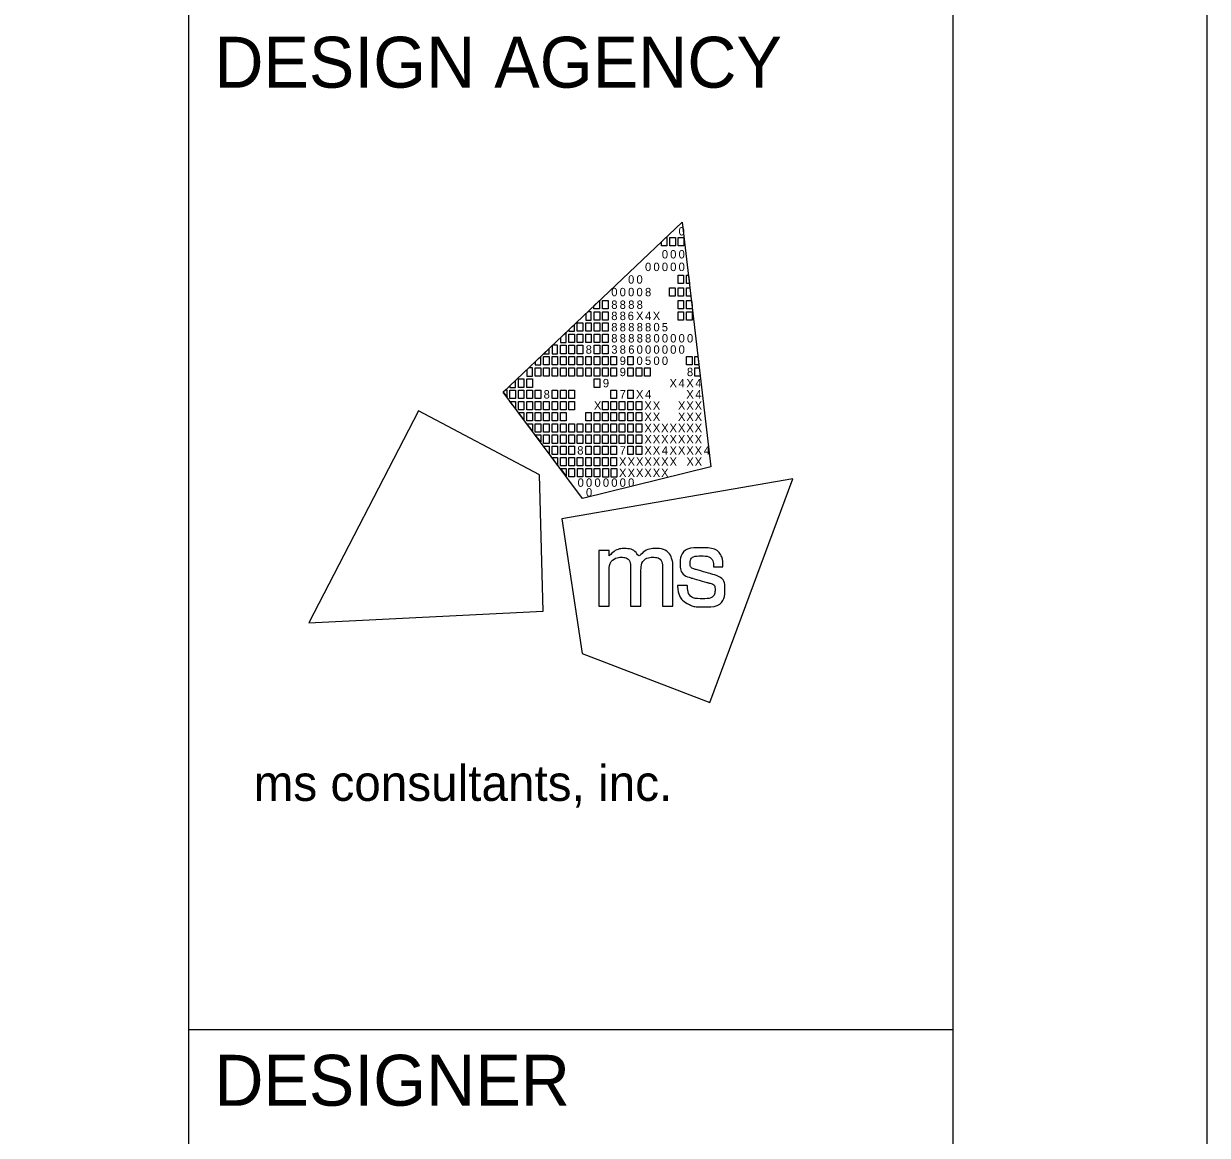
# Model space of a CAD drawing. Extents: x -3.2 to 34, y 0 to 22.
# Drawn here: x 31.676 to 34, y 2.292 to 4.476 of the extents above; entities that cross this region are included whole.
import ezdxf

# ---------------------------------------------------------------- set-up
doc = ezdxf.new("R2010")
doc.units = 0
for name, color, linetype in [('Default', 7, 'Continuous'), ('SH_Border', 7, 'Continuous'), ('SH_Cut_Line', 7, 'Continuous'), ('SH_Data', 7, 'Continuous')]:
    doc.layers.add(name, color=color, linetype=linetype)

msp = doc.modelspace()

# ---------------------------------------------------------------- linework, layer by layer
at = {"layer": 'Default'}
for p, q in [((32.6175, 3.7519), (32.9688, 4.0861)), ((32.9688, 4.0861), (32.9688, 4.0861)), ((32.9688, 4.0861), (33.0253, 3.6052)), ((32.773, 3.543), (32.6175, 3.7519)), ((33.0253, 3.6052), (32.773, 3.543))]:
    msp.add_line(p, q, dxfattribs=at)
for points in [[(32.9279, 4.0472), (32.9369, 4.0558), (32.9389, 4.0558), (32.9389, 4.0393), (32.9279, 4.0393)], [(32.9444, 4.0558), (32.9554, 4.0558), (32.9554, 4.0393), (32.9444, 4.0393)], [(32.9609, 4.0558), (32.9719, 4.0558), (32.9719, 4.0393), (32.9609, 4.0393)], [(32.9606, 3.9815), (32.9716, 3.9815), (32.9716, 3.965), (32.9606, 3.965)], [(32.9771, 3.9815), (32.9811, 3.9815), (32.983, 3.965), (32.9771, 3.965)], [(32.9441, 3.9567), (32.9551, 3.9567), (32.9551, 3.9402), (32.9441, 3.9402)], [(32.9606, 3.9567), (32.9716, 3.9567), (32.9716, 3.9402), (32.9606, 3.9402)], [(32.9771, 3.9567), (32.984, 3.9567), (32.9859, 3.9402), (32.9771, 3.9402)], [(32.7953, 3.9211), (32.8064, 3.9316), (32.8064, 3.9154), (32.7953, 3.9154)], [(32.8123, 3.9319), (32.8233, 3.9319), (32.8233, 3.9154), (32.8123, 3.9154)], [(32.9606, 3.9319), (32.9716, 3.9319), (32.9716, 3.9154), (32.9606, 3.9154)], [(32.9771, 3.9319), (32.9869, 3.9319), (32.9881, 3.9218), (32.9881, 3.9154), (32.9771, 3.9154)], [(32.7958, 3.9099), (32.8068, 3.9099), (32.8068, 3.8934), (32.7958, 3.8934)], [(32.8123, 3.9099), (32.8233, 3.9099), (32.8233, 3.8934), (32.8123, 3.8934)], [(32.9606, 3.9099), (32.9716, 3.9099), (32.9716, 3.8934), (32.9606, 3.8934)], [(32.9771, 3.9099), (32.9881, 3.9099), (32.9881, 3.8934), (32.9771, 3.8934)], [(32.7627, 3.8879), (32.7737, 3.8879), (32.7737, 3.8714), (32.7627, 3.8714)], [(32.7793, 3.8879), (32.7903, 3.8879), (32.7903, 3.8714), (32.7793, 3.8714)], [(32.7958, 3.8879), (32.8068, 3.8879), (32.8068, 3.8714), (32.7958, 3.8714)], [(32.8123, 3.8879), (32.8233, 3.8879), (32.8233, 3.8714), (32.8123, 3.8714)], [(32.7462, 3.8659), (32.7572, 3.8659), (32.7572, 3.8494), (32.7462, 3.8494)], [(32.7627, 3.8659), (32.7737, 3.8659), (32.7737, 3.8494), (32.7627, 3.8494)], [(32.7793, 3.8659), (32.7903, 3.8659), (32.7903, 3.8494), (32.7793, 3.8494)], [(32.7958, 3.8659), (32.8068, 3.8659), (32.8068, 3.8494), (32.7958, 3.8494)], [(32.8123, 3.8659), (32.8233, 3.8659), (32.8233, 3.8494), (32.8123, 3.8494)], [(32.7297, 3.8439), (32.7407, 3.8439), (32.7407, 3.8273), (32.7297, 3.8273)], [(32.7462, 3.8439), (32.7572, 3.8439), (32.7572, 3.8273), (32.7462, 3.8273)], [(32.7627, 3.8439), (32.7737, 3.8439), (32.7737, 3.8273), (32.7627, 3.8273)], [(32.7958, 3.8439), (32.8068, 3.8439), (32.8068, 3.8273), (32.7958, 3.8273)], [(32.8123, 3.8439), (32.8233, 3.8439), (32.8233, 3.8273), (32.8123, 3.8273)], [(32.6967, 3.8218), (32.7077, 3.8218), (32.7077, 3.8053), (32.6967, 3.8053)], [(32.7132, 3.8218), (32.7242, 3.8218), (32.7242, 3.8053), (32.7132, 3.8053)], [(32.7297, 3.8218), (32.7407, 3.8218), (32.7407, 3.8053), (32.7297, 3.8053)], [(32.7462, 3.8218), (32.7572, 3.8218), (32.7572, 3.8053), (32.7462, 3.8053)], [(32.7627, 3.8218), (32.7737, 3.8218), (32.7737, 3.8053), (32.7627, 3.8053)], [(32.7793, 3.8218), (32.7903, 3.8218), (32.7903, 3.8053), (32.7793, 3.8053)], [(32.7958, 3.8218), (32.8068, 3.8218), (32.8068, 3.8053), (32.7958, 3.8053)], [(32.8123, 3.8218), (32.8233, 3.8218), (32.8233, 3.8053), (32.8123, 3.8053)], [(32.8288, 3.8218), (32.8398, 3.8218), (32.8398, 3.8053), (32.8288, 3.8053)], [(32.8618, 3.8218), (32.8728, 3.8218), (32.8728, 3.8053), (32.8618, 3.8053)], [(32.9771, 3.8218), (32.9881, 3.8218), (32.9881, 3.8053), (32.9771, 3.8053)], [(32.9935, 3.8218), (32.9998, 3.8218), (33.0018, 3.8053), (32.9935, 3.8053)], [(32.6802, 3.7998), (32.6912, 3.7998), (32.6912, 3.7833), (32.6802, 3.7833)], [(32.6967, 3.7998), (32.7077, 3.7998), (32.7077, 3.7833), (32.6967, 3.7833)], [(32.7132, 3.7998), (32.7242, 3.7998), (32.7242, 3.7833), (32.7132, 3.7833)], [(32.7297, 3.7998), (32.7407, 3.7998), (32.7407, 3.7833), (32.7297, 3.7833)], [(32.7462, 3.7998), (32.7572, 3.7998), (32.7572, 3.7833), (32.7462, 3.7833)], [(32.7627, 3.7998), (32.7737, 3.7998), (32.7737, 3.7833), (32.7627, 3.7833)], [(32.7793, 3.7998), (32.7903, 3.7998), (32.7903, 3.7833), (32.7793, 3.7833)], [(32.7958, 3.7998), (32.8068, 3.7998), (32.8068, 3.7833), (32.7958, 3.7833)], [(32.8123, 3.7998), (32.8233, 3.7998), (32.8233, 3.7833), (32.8123, 3.7833)], [(32.8288, 3.7998), (32.8398, 3.7998), (32.8398, 3.7833), (32.8288, 3.7833)], [(32.8618, 3.7998), (32.8728, 3.7998), (32.8728, 3.7833), (32.8618, 3.7833)], [(32.8783, 3.7998), (32.8893, 3.7998), (32.8893, 3.7833), (32.8783, 3.7833)], [(32.8947, 3.7998), (32.9057, 3.7998), (32.9057, 3.7833), (32.8947, 3.7833)], [(32.9935, 3.7998), (33.0024, 3.7998), (33.0044, 3.7833), (32.9935, 3.7833)], [(32.6471, 3.7778), (32.6581, 3.7778), (32.6581, 3.7613), (32.6471, 3.7613)], [(32.6637, 3.7778), (32.6747, 3.7778), (32.6747, 3.7613), (32.6637, 3.7613)], [(32.7958, 3.7778), (32.8068, 3.7778), (32.8068, 3.7613), (32.7958, 3.7613)], [(32.6306, 3.7558), (32.6416, 3.7558), (32.6416, 3.7393), (32.6306, 3.7393)], [(32.6471, 3.7558), (32.6581, 3.7558), (32.6581, 3.7393), (32.6471, 3.7393)], [(32.6637, 3.7558), (32.6747, 3.7558), (32.6747, 3.7393), (32.6637, 3.7393)], [(32.6802, 3.7558), (32.6912, 3.7558), (32.6912, 3.7393), (32.6802, 3.7393)], [(32.7132, 3.7558), (32.7242, 3.7558), (32.7242, 3.7393), (32.7132, 3.7393)], [(32.7297, 3.7558), (32.7407, 3.7558), (32.7407, 3.7393), (32.7297, 3.7393)], [(32.7462, 3.7558), (32.7572, 3.7558), (32.7572, 3.7393), (32.7462, 3.7393)], [(32.8288, 3.7558), (32.8398, 3.7558), (32.8398, 3.7393), (32.8288, 3.7393)], [(32.8618, 3.7558), (32.8728, 3.7558), (32.8728, 3.7393), (32.8618, 3.7393)], [(32.6306, 3.7338), (32.6416, 3.7338), (32.6416, 3.72)], [(32.6471, 3.7338), (32.6581, 3.7338), (32.6581, 3.7173), (32.6471, 3.7173)], [(32.6637, 3.7338), (32.6747, 3.7338), (32.6747, 3.7173), (32.6637, 3.7173)], [(32.6802, 3.7338), (32.6912, 3.7338), (32.6912, 3.7173), (32.6802, 3.7173)], [(32.6967, 3.7338), (32.7077, 3.7338), (32.7077, 3.7173), (32.6967, 3.7173)], [(32.7132, 3.7338), (32.7242, 3.7338), (32.7242, 3.7173), (32.7132, 3.7173)], [(32.7297, 3.7338), (32.7407, 3.7338), (32.7407, 3.7173), (32.7297, 3.7173)], [(32.7462, 3.7338), (32.7572, 3.7338), (32.7572, 3.7173), (32.7462, 3.7173)], [(32.8123, 3.7338), (32.8233, 3.7338), (32.8233, 3.7173), (32.8123, 3.7173)], [(32.8288, 3.7338), (32.8398, 3.7338), (32.8398, 3.7173), (32.8288, 3.7173)], [(32.8453, 3.7338), (32.8563, 3.7338), (32.8563, 3.7173), (32.8453, 3.7173)], [(32.8618, 3.7338), (32.8728, 3.7338), (32.8728, 3.7173), (32.8618, 3.7173)], [(32.8783, 3.7338), (32.8893, 3.7338), (32.8893, 3.7173), (32.8783, 3.7173)], [(32.6471, 3.7117), (32.6581, 3.7117), (32.6581, 3.698)], [(32.6637, 3.7117), (32.6747, 3.7117), (32.6747, 3.6952), (32.6637, 3.6952)], [(32.6802, 3.7117), (32.6912, 3.7117), (32.6912, 3.6952), (32.6802, 3.6952)], [(32.6967, 3.7117), (32.7077, 3.7117), (32.7077, 3.6952), (32.6967, 3.6952)], [(32.7132, 3.7117), (32.7242, 3.7117), (32.7242, 3.6952), (32.7132, 3.6952)], [(32.7297, 3.7117), (32.7407, 3.7117), (32.7407, 3.6952), (32.7297, 3.6952)], [(32.7793, 3.7117), (32.7903, 3.7117), (32.7903, 3.6952), (32.7793, 3.6952)], [(32.7958, 3.7117), (32.8068, 3.7117), (32.8068, 3.6952), (32.7958, 3.6952)], [(32.8123, 3.7117), (32.8233, 3.7117), (32.8233, 3.6952), (32.8123, 3.6952)], [(32.8288, 3.7117), (32.8398, 3.7117), (32.8398, 3.6952), (32.8288, 3.6952)], [(32.8453, 3.7117), (32.8563, 3.7117), (32.8563, 3.6952), (32.8453, 3.6952)], [(32.8618, 3.7117), (32.8728, 3.7117), (32.8728, 3.6952), (32.8618, 3.6952)], [(32.8783, 3.7117), (32.8893, 3.7117), (32.8893, 3.6952), (32.8783, 3.6952)], [(32.6637, 3.6897), (32.6747, 3.6897), (32.6747, 3.676)], [(32.6747, 3.6897), (32.6747, 3.6897), (32.6747, 3.6897)], [(32.6802, 3.6897), (32.6912, 3.6897), (32.6912, 3.6732), (32.6802, 3.6732)], [(32.6967, 3.6897), (32.7077, 3.6897), (32.7077, 3.6732), (32.6967, 3.6732)], [(32.7132, 3.6897), (32.7242, 3.6897), (32.7242, 3.6732), (32.7132, 3.6732)], [(32.7297, 3.6897), (32.7407, 3.6897), (32.7407, 3.6732), (32.7297, 3.6732)], [(32.7462, 3.6897), (32.7572, 3.6897), (32.7572, 3.6732), (32.7462, 3.6732)], [(32.7627, 3.6897), (32.7737, 3.6897), (32.7737, 3.6732), (32.7627, 3.6732)], [(32.7793, 3.6897), (32.7903, 3.6897), (32.7903, 3.6732), (32.7793, 3.6732)], [(32.7958, 3.6897), (32.8068, 3.6897), (32.8068, 3.6732), (32.7958, 3.6732)], [(32.8123, 3.6897), (32.8233, 3.6897), (32.8233, 3.6732), (32.8123, 3.6732)], [(32.8288, 3.6897), (32.8398, 3.6897), (32.8398, 3.6732), (32.8288, 3.6732)], [(32.8453, 3.6897), (32.8563, 3.6897), (32.8563, 3.6732), (32.8453, 3.6732)], [(32.8618, 3.6897), (32.8728, 3.6897), (32.8728, 3.6732), (32.8618, 3.6732)], [(32.8783, 3.6897), (32.8893, 3.6897), (32.8893, 3.6732), (32.8783, 3.6732)], [(32.6802, 3.6677), (32.6912, 3.6677), (32.6912, 3.654)], [(32.6967, 3.6677), (32.7077, 3.6677), (32.7077, 3.6512), (32.6967, 3.6512)], [(32.7132, 3.6677), (32.7242, 3.6677), (32.7242, 3.6512), (32.7132, 3.6512)], [(32.7297, 3.6677), (32.7407, 3.6677), (32.7407, 3.6512), (32.7297, 3.6512)], [(32.7462, 3.6677), (32.7572, 3.6677), (32.7572, 3.6512), (32.7462, 3.6512)], [(32.7627, 3.6677), (32.7737, 3.6677), (32.7737, 3.6512), (32.7627, 3.6512)], [(32.7793, 3.6677), (32.7903, 3.6677), (32.7903, 3.6512), (32.7793, 3.6512)], [(32.7958, 3.6677), (32.8068, 3.6677), (32.8068, 3.6512), (32.7958, 3.6512)], [(32.8123, 3.6677), (32.8233, 3.6677), (32.8233, 3.6512), (32.8123, 3.6512)], [(32.8288, 3.6677), (32.8398, 3.6677), (32.8398, 3.6512), (32.8288, 3.6512)], [(32.8453, 3.6677), (32.8563, 3.6677), (32.8563, 3.6512), (32.8453, 3.6512)], [(32.8618, 3.6677), (32.8728, 3.6677), (32.8728, 3.6512), (32.8618, 3.6512)], [(32.8783, 3.6677), (32.8893, 3.6677), (32.8893, 3.6512), (32.8783, 3.6512)], [(32.7077, 3.6305), (32.6965, 3.6457), (32.7077, 3.6457)], [(32.7132, 3.6457), (32.7242, 3.6457), (32.7242, 3.6292), (32.7132, 3.6292)], [(32.7297, 3.6457), (32.7407, 3.6457), (32.7407, 3.6292), (32.7297, 3.6292)], [(32.7462, 3.6457), (32.7572, 3.6457), (32.7572, 3.6292), (32.7462, 3.6292)], [(32.7793, 3.6457), (32.7903, 3.6457), (32.7903, 3.6292), (32.7793, 3.6292)], [(32.7958, 3.6457), (32.8068, 3.6457), (32.8068, 3.6292), (32.7958, 3.6292)], [(32.8123, 3.6457), (32.8233, 3.6457), (32.8233, 3.6292), (32.8123, 3.6292)], [(32.8288, 3.6457), (32.8398, 3.6457), (32.8398, 3.6292), (32.8288, 3.6292)], [(32.8618, 3.6457), (32.8728, 3.6457), (32.8728, 3.6292), (32.8618, 3.6292)], [(32.8783, 3.6457), (32.8893, 3.6457), (32.8893, 3.6292), (32.8783, 3.6292)], [(32.724, 3.6082), (32.7132, 3.6237), (32.7242, 3.6237)], [(32.7297, 3.6237), (32.7407, 3.6237), (32.7407, 3.6072), (32.7297, 3.6072)], [(32.7462, 3.6237), (32.7572, 3.6237), (32.7572, 3.6072), (32.7462, 3.6072)], [(32.7627, 3.6237), (32.7737, 3.6237), (32.7737, 3.6072), (32.7627, 3.6072)], [(32.7793, 3.6237), (32.7903, 3.6237), (32.7903, 3.6072), (32.7793, 3.6072)], [(32.7958, 3.6237), (32.8068, 3.6237), (32.8068, 3.6072), (32.7958, 3.6072)], [(32.8123, 3.6237), (32.8233, 3.6237), (32.8233, 3.6072), (32.8123, 3.6072)], [(32.8288, 3.6237), (32.8398, 3.6237), (32.8398, 3.6072), (32.8288, 3.6072)], [(32.7302, 3.6017), (32.7407, 3.6017), (32.7408, 3.5875)], [(32.7463, 3.6017), (32.7573, 3.6017), (32.7573, 3.5852), (32.7463, 3.5852)], [(32.763, 3.6017), (32.774, 3.6017), (32.774, 3.5852), (32.763, 3.5852)], [(32.7794, 3.6017), (32.7904, 3.6017), (32.7904, 3.5852), (32.7794, 3.5852)], [(32.796, 3.6017), (32.807, 3.6017), (32.807, 3.5852), (32.796, 3.5852)], [(32.8129, 3.6017), (32.8239, 3.6017), (32.8239, 3.5851), (32.8129, 3.5851)], [(32.8296, 3.6017), (32.8406, 3.6017), (32.8406, 3.5851), (32.8296, 3.5851)]]:
    msp.add_lwpolyline(points, close=True, dxfattribs=at)
for points in [[(32.7903, 3.9099), (32.7836, 3.9099), (32.7793, 3.9058), (32.7793, 3.8934), (32.7903, 3.8934), (32.7903, 3.9099)], [(32.7572, 3.8849), (32.7462, 3.8744), (32.7462, 3.8714), (32.7572, 3.8714), (32.7572, 3.8849)], [(32.7407, 3.8691), (32.7297, 3.8587), (32.7297, 3.8494), (32.7407, 3.8494), (32.7407, 3.8691)], [(32.7077, 3.8377), (32.6968, 3.8273), (32.7077, 3.8273), (32.7077, 3.8377)], [(32.7242, 3.8439), (32.7141, 3.8439), (32.7132, 3.843), (32.7132, 3.8273), (32.7242, 3.8273), (32.7242, 3.8439)], [(32.6912, 3.822), (32.6802, 3.8115), (32.6802, 3.8053), (32.6912, 3.8053), (32.6912, 3.822)], [(32.6747, 3.7998), (32.6679, 3.7998), (32.6637, 3.7958), (32.6637, 3.7833), (32.6747, 3.7833), (32.6747, 3.7998)], [(32.6416, 3.7749), (32.6306, 3.7644), (32.6306, 3.7613), (32.6416, 3.7613), (32.6416, 3.7749)], [(32.6251, 3.7558), (32.6216, 3.7558), (32.6175, 3.7519), (32.6251, 3.7417), (32.6251, 3.7558)], [(32.4512, 3.7149), (32.2359, 3.2988), (32.6956, 3.3215), (32.6884, 3.5892), (32.4512, 3.7149)], [(33.0229, 3.1422), (33.1859, 3.5814), (32.7324, 3.5029), (32.7722, 3.2381), (33.0229, 3.1422)]]:
    msp.add_lwpolyline(points, dxfattribs=at)
for points in [[(32.8048, 3.3315), (32.8048, 3.3315), (32.8048, 3.4409), (32.8048, 3.4409), (32.8048, 3.4409), (32.8255, 3.4409), (32.8255, 3.4409), (32.8255, 3.4409), (32.8255, 3.4297), (32.8255, 3.4297), (32.8346, 3.4399), (32.8457, 3.4445), (32.8555, 3.4445), (32.8688, 3.4445), (32.8791, 3.4372), (32.8837, 3.4266), (32.8915, 3.4381), (32.905, 3.4446), (32.9166, 3.4446), (32.9325, 3.4446), (32.9451, 3.435), (32.9494, 3.4213), (32.9494, 3.4212), (32.9494, 3.4212), (32.9494, 3.4212), (32.9501, 3.419), (32.9506, 3.4172), (32.9506, 3.4071), (32.9506, 3.4071), (32.9506, 3.3314), (32.9506, 3.3314), (32.9506, 3.3314), (32.9303, 3.3314), (32.9303, 3.3314), (32.9303, 3.3314), (32.9303, 3.4048), (32.9303, 3.4048), (32.9303, 3.4201), (32.9219, 3.4274), (32.911, 3.4274), (32.8995, 3.4274), (32.8879, 3.4171), (32.8879, 3.4001), (32.8879, 3.4001), (32.8879, 3.3315), (32.8879, 3.3315), (32.8879, 3.3315), (32.8674, 3.3315), (32.8674, 3.3315), (32.8674, 3.3315), (32.8674, 3.4059), (32.8674, 3.4059), (32.8674, 3.4203), (32.8588, 3.4274), (32.8496, 3.4274), (32.8384, 3.4274), (32.8254, 3.417), (32.8254, 3.3962), (32.8254, 3.3962), (32.8254, 3.3315), (32.8254, 3.3315), (32.8254, 3.3315), (32.8048, 3.3315), (32.8048, 3.3315)], [(32.9595, 3.3709), (32.9595, 3.3709), (32.9595, 3.3717), (32.9595, 3.3717), (32.9595, 3.3717), (32.9603, 3.3717), (32.9603, 3.3717), (32.9603, 3.3717), (32.9783, 3.3717), (32.9783, 3.3717), (32.9783, 3.3717), (32.9789, 3.3717), (32.9789, 3.3717), (32.9789, 3.3717), (32.979, 3.371), (32.979, 3.371), (32.9803, 3.3554), (32.9887, 3.346), (33.009, 3.346), (33.0273, 3.346), (33.0333, 3.3554), (33.0333, 3.3631), (33.0333, 3.3732), (33.0256, 3.3758), (33.0175, 3.378), (33.0175, 3.378), (32.987, 3.3867), (32.987, 3.3867), (32.972, 3.3909), (32.9648, 3.4019), (32.9648, 3.4142), (32.9648, 3.4303), (32.9768, 3.4462), (33.0052, 3.4462), (33.0348, 3.4462), (33.0489, 3.4285), (33.0489, 3.4095), (33.0489, 3.4095), (33.0489, 3.4087), (33.0489, 3.4087), (33.0489, 3.4087), (33.0482, 3.4087), (33.0482, 3.4087), (33.0482, 3.4087), (33.0312, 3.4087), (33.0312, 3.4087), (33.0312, 3.4087), (33.0305, 3.4087), (33.0305, 3.4087), (33.0305, 3.4087), (33.0305, 3.4094), (33.0305, 3.4094), (33.0301, 3.4208), (33.0226, 3.43), (33.0056, 3.43), (32.9891, 3.43), (32.9843, 3.4218), (32.9843, 3.4157), (32.9843, 3.4108), (32.9869, 3.4059), (32.9959, 3.4033), (32.9959, 3.4033), (33.0255, 3.3948), (33.0255, 3.3948), (33.0462, 3.3889), (33.0527, 3.3777), (33.0527, 3.3639), (33.0527, 3.3462), (33.041, 3.3298), (33.0087, 3.3298), (32.9952, 3.3298), (32.9877, 3.3321), (32.9823, 3.3348), (32.969, 3.3414), (32.9609, 3.3536), (32.9595, 3.3709)]]:
    msp.add_open_spline(points, degree=3, dxfattribs=at)
at = {"layer": 'SH_Border'}
for p, q in [((32, 0.5), (32, 21.5)), ((32, 2.5), (33.5, 2.5))]:
    msp.add_line(p, q, dxfattribs=at)
msp.add_lwpolyline([(1.5, 21.5), (33.5, 21.5), (33.5, 0.5), (1.5, 0.5)], close=True, dxfattribs=at)
at = {"layer": 'SH_Cut_Line'}
msp.add_lwpolyline([(0, 0), (34, 0), (34, 22), (0, 22)], close=True, dxfattribs=at)
at = {"layer": 'SH_Data'}
msp.add_line((32.75, 3.5), (32.75, 3.5), dxfattribs=at)

# ---------------------------------------------------------------- texts
at = {"layer": 'Default'}
for s, p in [('0', (32.9617, 4.0597)), ('0', (32.9288, 4.0145)), ('0', (32.9452, 4.0145)), ('0', (32.9617, 4.0145)), ('0', (32.8958, 3.9897)), ('0', (32.9123, 3.9897)), ('0', (32.9288, 3.9897)), ('0', (32.9452, 3.9897)), ('0', (32.9617, 3.9897)), ('0', (32.8625, 3.965)), ('0', (32.879, 3.965)), ('0', (32.8295, 3.9402)), ('0', (32.846, 3.9402)), ('0', (32.8625, 3.9402)), ('0', (32.879, 3.9402)), ('8', (32.8958, 3.9402)), ('8', (32.8295, 3.9154)), ('8', (32.846, 3.9154)), ('8', (32.8628, 3.9154)), ('8', (32.8793, 3.9154)), ('8', (32.8295, 3.8934)), ('8', (32.846, 3.8934)), ('6', (32.8618, 3.8934)), ('X', (32.8781, 3.8934)), ('4', (32.8958, 3.8934)), ('X', (32.911, 3.8934)), ('8', (32.8295, 3.8713)), ('8', (32.846, 3.8713)), ('8', (32.8628, 3.8713)), ('8', (32.8794, 3.8713)), ('8', (32.8958, 3.8713)), ('0', (32.9123, 3.8713)), ('5', (32.9287, 3.8713)), ('8', (32.8295, 3.8494)), ('8', (32.846, 3.8494)), ('8', (32.8628, 3.8494)), ('8', (32.8794, 3.8494)), ('8', (32.8958, 3.8494)), ('0', (32.9123, 3.8494)), ('0', (32.9288, 3.8494)), ('0', (32.9452, 3.8494)), ('0', (32.9617, 3.8494)), ('0', (32.9782, 3.8494)), ('8', (32.7793, 3.8273)), ('3', (32.8295, 3.8273)), ('8', (32.846, 3.8273)), ('6', (32.8629, 3.8273)), ('0', (32.8793, 3.8273)), ('0', (32.8958, 3.8273)), ('0', (32.9123, 3.8273)), ('0', (32.9288, 3.8273)), ('0', (32.9452, 3.8273)), ('0', (32.9617, 3.8273)), ('9', (32.846, 3.8053)), ('0', (32.879, 3.8053)), ('5', (32.8957, 3.8053)), ('0', (32.9123, 3.8053)), ('0', (32.9288, 3.8053)), ('9', (32.846, 3.7833)), ('8', (32.9781, 3.7833)), ('9', (32.813, 3.7613)), ('X', (32.9439, 3.7613)), ('4', (32.9617, 3.7613)), ('X', (32.9769, 3.7613)), ('4', (32.9946, 3.7613)), ('8', (32.6967, 3.7393)), ('7', (32.846, 3.7393)), ('X', (32.8781, 3.7393)), ('4', (32.8958, 3.7393)), ('X', (32.9769, 3.7393)), ('4', (32.9946, 3.7393)), ('X', (32.7955, 3.7173)), ('X', (32.8945, 3.7173)), ('X', (32.911, 3.7173)), ('X', (32.9604, 3.7173)), ('X', (32.9769, 3.7173)), ('X', (32.9933, 3.7173)), ('X', (32.8945, 3.6952)), ('X', (32.911, 3.6952)), ('X', (32.9604, 3.6952)), ('X', (32.9769, 3.6952)), ('X', (32.9933, 3.6952)), ('X', (32.8945, 3.6732)), ('X', (32.911, 3.6732)), ('X', (32.9274, 3.6732)), ('X', (32.9439, 3.6732)), ('X', (32.9604, 3.6732)), ('X', (32.9769, 3.6732)), ('X', (32.9933, 3.6732)), ('X', (32.8945, 3.6512)), ('X', (32.911, 3.6512)), ('X', (32.9274, 3.6512)), ('X', (32.9439, 3.6512)), ('X', (32.9604, 3.6512)), ('X', (32.9769, 3.6512)), ('X', (32.9933, 3.6512)), ('8', (32.7627, 3.6292)), ('7', (32.846, 3.6292)), ('X', (32.8945, 3.6292)), ('X', (32.911, 3.6292)), ('4', (32.9288, 3.6292)), ('X', (32.9439, 3.6292)), ('X', (32.9604, 3.6292)), ('X', (32.9769, 3.6292)), ('X', (32.9933, 3.6292)), ('4', (33.0111, 3.6292)), ('X', (32.8447, 3.6072)), ('X', (32.8616, 3.6072)), ('X', (32.878, 3.6072)), ('X', (32.8945, 3.6072)), ('X', (32.911, 3.6072)), ('X', (32.9274, 3.6072)), ('X', (32.9439, 3.6072)), ('X', (32.9771, 3.6072)), ('X', (32.9933, 3.6072)), ('0', (32.7634, 3.5659)), ('0', (32.7799, 3.5659)), ('0', (32.7965, 3.5659)), ('0', (32.813, 3.5659)), ('0', (32.8295, 3.5659)), ('X', (32.8447, 3.5851)), ('0', (32.846, 3.5659)), ('X', (32.8616, 3.5851)), ('0', (32.8625, 3.5659)), ('X', (32.878, 3.5851)), ('X', (32.8945, 3.5851)), ('X', (32.911, 3.5851)), ('X', (32.9274, 3.5851)), ('0', (32.7799, 3.5467))]:
    msp.add_text(s, height=0.0165, rotation=360, dxfattribs=at).set_placement(p)
at = {"layer": 'SH_Border'}
msp.add_text('ms consultants, inc.', height=0.07, rotation=360, dxfattribs=at).set_placement((32.1273, 2.9489))
at = {"layer": 'SH_Data'}
for s, p in [('DESIGN AGENCY', (32.05, 4.35)), ('DESIGNER', (32.05, 2.35))]:
    msp.add_text(s, height=0.1, dxfattribs=at).set_placement(p)

doc.saveas('drawing.dxf')
